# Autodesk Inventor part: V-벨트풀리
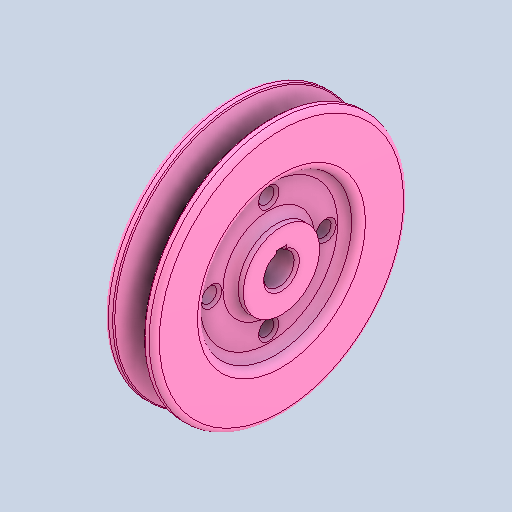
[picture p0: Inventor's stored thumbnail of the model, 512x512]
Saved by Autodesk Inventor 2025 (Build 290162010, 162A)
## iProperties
Created: 2024-07
Part Number: V-벨트풀리
Material: 강철, 연강
Document SubType Name: Modeling
Designer: Admin
Density: 7.86 g/cm^3
Appearance: 기본값
Author: jhkim
Sending System: Autodesk Inventor 2025
Preprocessor: ST-DEVELOPER v20
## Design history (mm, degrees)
feature "솔리드1"
node "솔리드2"
